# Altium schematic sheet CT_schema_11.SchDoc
size 254 x 194 mm
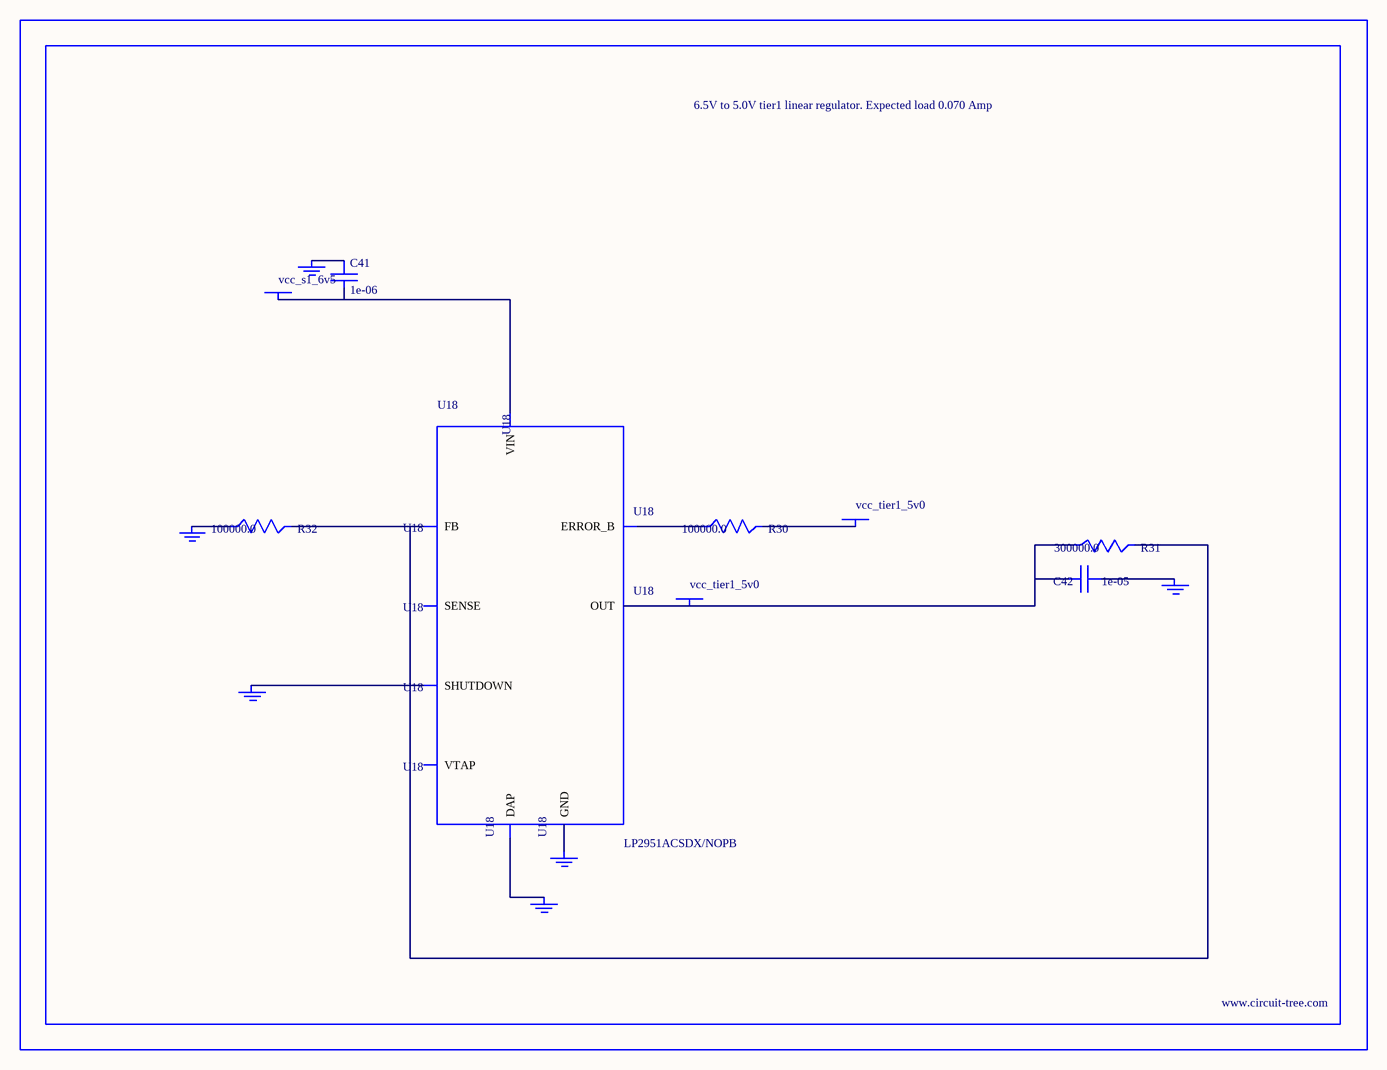
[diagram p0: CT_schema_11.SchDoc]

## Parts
BORDER10  (no value)
C41  1e-06  [C0603]
C42  1e-05  [C1210]
GND_INSTANCE_10_0  (no value)
GND_INSTANCE_10_1  (no value)
GND_INSTANCE_10_2  (no value)
GND_INSTANCE_10_3  (no value)
GND_INSTANCE_10_4  (no value)
GND_INSTANCE_10_5  (no value)
POWER_INSTANCE_10_0  vcc_tier1_5v0
POWER_INSTANCE_10_1  vcc_s1_6v5
POWER_INSTANCE_10_2  vcc_tier1_5v0
R30  100000.0  [R0603]
R31  300000.0  [R0603]
R32  100000.0  [R0603]
U18  LP2951ACSDX/NOPB  [WSON-8]

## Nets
NetC41_1: C41.1 GND_INSTANCE_10_3.0(GND)
NetC41_2: C41.2 POWER_INSTANCE_10_1.0(PWR) U18.8(VIN)
NetC42_1: C42.1 GND_INSTANCE_10_0.0(GND)
NetC42_2: C42.2 POWER_INSTANCE_10_2.0(PWR) R31.1 U18.1(OUT)
NetGND_INSTANCE_10_1_0: GND_INSTANCE_10_1.0(GND) U18.3(SHUTDOWN)
NetGND_INSTANCE_10_2_0: GND_INSTANCE_10_2.0(GND) R32.1
NetGND_INSTANCE_10_4_0: GND_INSTANCE_10_4.0(GND) U18.PAD(DAP)
NetGND_INSTANCE_10_5_0: GND_INSTANCE_10_5.0(GND) U18.4(GND)
NetPOWER_INSTANCE_10_0_0: POWER_INSTANCE_10_0.0(PWR) R30.2
NetR30_1: R30.1 U18.5(ERROR_B)
NetR31_2: R31.2 R32.2 U18.7(FB)

Not connected (* = marked no-connect by the designer): U18 2(SENSE) 6(VTAP)

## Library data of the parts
BORDER10 = BORDER_PAGE10
C41 = C0603C105K3RACTU
C42 = GRM32DR61E106MA12L
GND_INSTANCE_10_0-GND_INSTANCE_10_5 = GND
POWER_INSTANCE_10_0-POWER_INSTANCE_10_2 = PWR
R30 R32 = RC0603JR-07100KL
R31 = RC0603JR-07300KL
